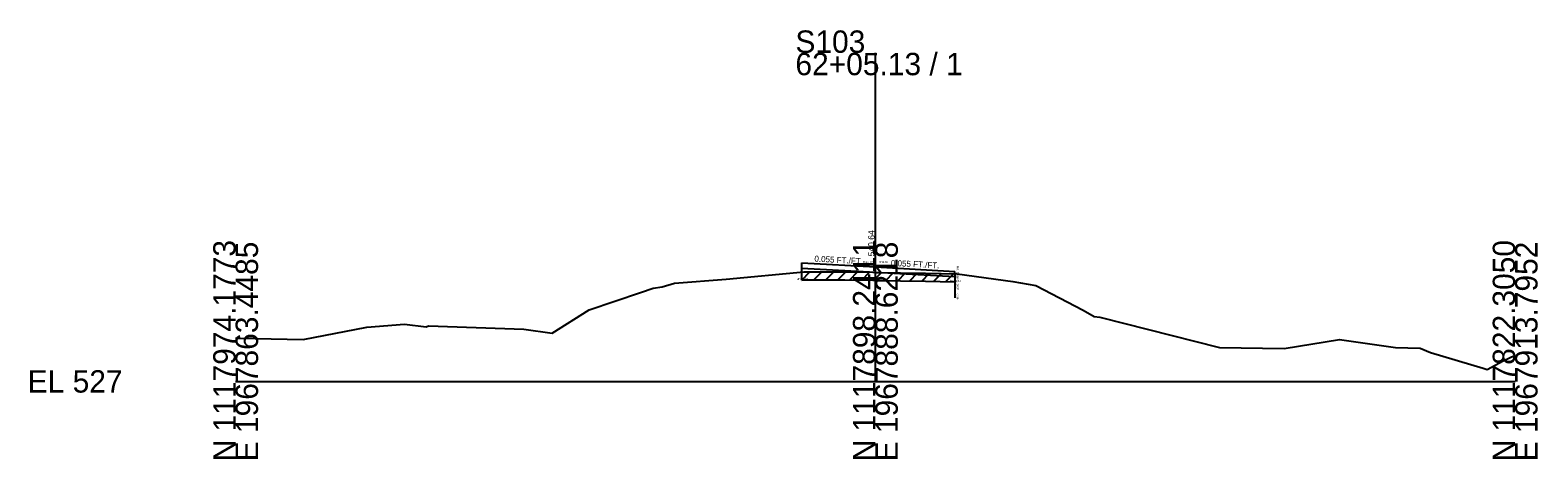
# Model space of a CAD drawing. Extents: x -26 to 163, y -10 to 24018.
# Drawn here: x -25.7 to 162.8, y 9990.3 to 10044 of the extents above; entities that cross this region are included whole.
import ezdxf

# ---------------------------------------------------------------- set-up
doc = ezdxf.new("R2010")
doc.units = 0
for name, color, linetype in [('RD_GPK_XS_Cell', 7, 'Continuous'), ('RD_XS_ExGround', 7, 'Continuous'), ('RD_XS_ExPaveRet', 7, 'Continuous'), ('RD_XS_Misc_Line', 7, 'Continuous'), ('RD_XS_PaveOvlay_CP', 7, 'Continuous'), ('RD_XS_TX_Elev_EX', 7, 'Continuous'), ('RD_XS_TX_ExEOP', 7, 'Continuous'), ('RD_XS_TX_Notes', 7, 'Continuous'), ('RD_XS_TX_Profile', 7, 'Continuous'), ('RD_XS_TX_Slope', 7, 'Continuous')]:
    doc.layers.add(name, color=color, linetype=linetype)

msp = doc.modelspace()

# ---------------------------------------------------------------- linework, layer by layer
at = {"layer": 'RD_GPK_XS_Cell'}
for p, q in [((80, 10000), (80, 10041.11)), ((0, 10000), (80, 10000)), ((80, 10000), (160, 10000))]:
    msp.add_line(p, q, dxfattribs=at)
at = {"layer": 'RD_XS_ExGround'}
msp.add_lwpolyline([(0, 10005.4), (0.45, 10005.39), (8.43, 10005.23), (16.42, 10006.78), (21.1, 10007.15), (23.83, 10006.83), (24.13, 10006.95), (36.03, 10006.53), (39.6, 10006.05), (44.22, 10008.97), (50.62, 10011.12), (52.23, 10011.65), (53.32, 10011.84), (54.9, 10012.3), (61.33, 10012.8), (71.07, 10013.7), (76.16, 10013.7), (79.68, 10013.67), (80, 10013.64), (86.26, 10013.56), (90.22, 10013.45), (97.18, 10012.52), (100.08, 10011.99), (105.97, 10008.93), (107.37, 10008.1), (108.07, 10008.04), (123.05, 10004.25), (131.1, 10004.1), (138.04, 10005.26), (145.06, 10004.24), (148.14, 10004.17), (149.4, 10003.61), (156.02, 10001.64), (156.49, 10001.48), (158.52, 10002.58), (160, 10003.28)], dxfattribs=at)
at = {"layer": 'RD_XS_ExPaveRet'}
for p, q in [((70.79, 10012.68), (71.82, 10013.7)), ((70.79, 10012.68), (70.79, 10013.68)), ((72.29, 10012.7), (73.29, 10013.7)), ((73.79, 10012.7), (74.79, 10013.7)), ((75.29, 10012.7), (76.29, 10013.7)), ((76.79, 10012.69), (77.78, 10013.69)), ((78.29, 10012.68), (79.28, 10013.67)), ((79.79, 10012.66), (80.76, 10013.63)), ((81.29, 10012.62), (82.28, 10013.61)), ((82.79, 10012.6), (83.78, 10013.59)), ((84.29, 10012.58), (85.28, 10013.57)), ((85.79, 10012.56), (86.77, 10013.54)), ((87.29, 10012.53), (88.27, 10013.5)), ((88.79, 10012.49), (89.77, 10013.46)), ((89.92, 10013.45), (89.92, 10012.45)), ((70.79, 10012.68), (71.07, 10012.7)), ((71.07, 10012.7), (76.16, 10012.7)), ((76.16, 10012.7), (79.68, 10012.67)), ((79.68, 10012.67), (80, 10012.64)), ((80, 10012.64), (86.26, 10012.56)), ((86.26, 10012.56), (89.92, 10012.45))]:
    msp.add_line(p, q, dxfattribs=at)
at = {"layer": 'RD_XS_Misc_Line'}
msp.add_line((89.92, 10013.45), (89.92, 10010.45), dxfattribs=at)
at = {"layer": 'RD_XS_PaveOvlay_CP'}
for p, q in [((70.79, 10014.82), (80, 10014.32)), ((70.79, 10013.68), (70.79, 10014.82)), ((80, 10013.64), (70.79, 10014.14)), ((80, 10014.32), (89.92, 10013.77)), ((89.92, 10013.09), (80, 10013.64)), ((89.92, 10013.45), (89.92, 10013.77))]:
    msp.add_line(p, q, dxfattribs=at)

# ---------------------------------------------------------------- texts
at = {"layer": 'RD_GPK_XS_Cell'}
for s, p in [('S103', (70, 10041.11)), ('62+05.13 / 1', (70, 10038.31)), ('EL 527', (-26, 9998.6))]:
    msp.add_text(s, height=2.8, dxfattribs=at).set_placement(p)
for s, p in [('N 1117974.1773', (0, 9990)), ('E 1967863.4485', (2.8, 9990)), ('N 1117898.2411', (80, 9990)), ('E 1967888.6218', (82.8, 9990)), ('N 1117822.3050', (160, 9990)), ('E 1967913.7952', (162.8, 9990))]:
    msp.add_text(s, height=2.8, rotation=90, dxfattribs=at).set_placement(p)
at = {"layer": 'RD_XS_TX_Elev_EX'}
msp.add_text('540.64', height=0.8, rotation=90, dxfattribs=at).set_placement((79.9, 10015.64))
at = {"layer": 'RD_XS_TX_ExEOP'}
for s, p in [('EOP-L', (70.74, 10014.82)), ('EOP-R', (89.87, 10013.77))]:
    msp.add_text(s, height=0.1, rotation=270, dxfattribs=at).set_placement(p)
at = {"layer": 'RD_XS_TX_Notes'}
for s, p in [('Elev. @CL = 541.32', (78.47, 10014.82)), (' dE= 1.15', (70.09, 10012.68)), (' dE= 0.68', (79.29, 10012.64)), (' dE= 0.32', (89.2, 10012.45))]:
    msp.add_text(s, height=0.25, dxfattribs=at).set_placement(p)
msp.add_text(' Min. Distance @CP = -0.36', height=0.25, rotation=270, dxfattribs=at).set_placement((90.17, 10014.55))
at = {"layer": 'RD_XS_TX_Profile'}
msp.add_text('CL', height=0.25, dxfattribs=at).set_placement((79.77, 10014.32))
at = {"layer": 'RD_XS_TX_Slope'}
for p in [(72.36, 10014.99), (81.92, 10014.46)]:
    msp.add_text('0.055 FT./FT.', height=0.75, rotation=356.8574, dxfattribs=at).set_placement(p)

doc.saveas('drawing.dxf')
